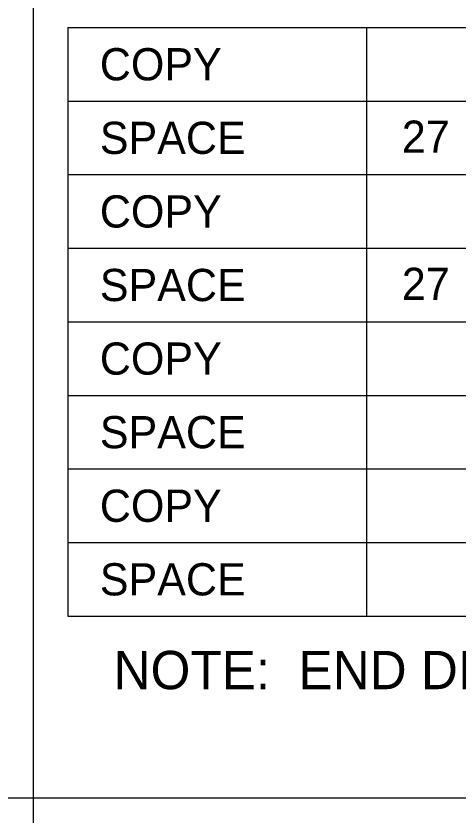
# Model space of a CAD drawing. Extents: x 10268312 to 10268472, y 2142583 to 2142688.
# Drawn here: x 10268394.36 to 10268403.97, y 2142639.91 to 2142657.28 of the extents above; entities that cross this region are included whole.
import ezdxf

# ---------------------------------------------------------------- set-up
doc = ezdxf.new("R2010")
doc.units = 0
for name, color, linetype in [('SheetBorder_dp', 7, 'Continuous'), ('SumBoxLines_dp', 7, 'Continuous'), ('SumBoxLinesMin_dp', 7, 'Continuous'), ('TextLabel', 7, 'Continuous'), ('TextMisc', 7, 'Continuous'), ('TextNotes', 7, 'Continuous')]:
    doc.layers.add(name, color=color, linetype=linetype)

msp = doc.modelspace()

# ---------------------------------------------------------------- linework, layer by layer
at = {"layer": 'SheetBorder_dp'}
for p, q in [((10268394.73, 2142688.282), (10268394.73, 2142592.282)), ((10268317.73, 2142640.282), (10268471.73, 2142640.282))]:
    msp.add_line(p, q, dxfattribs=at)
at = {"layer": 'SumBoxLines_dp'}
for p, q in [((10268395.48, 2142657.032), (10268470.98, 2142657.032)), ((10268395.48, 2142657.032), (10268395.48, 2142644.232)), ((10268401.98, 2142657.032), (10268401.98, 2142644.232)), ((10268395.48, 2142653.832), (10268470.98, 2142653.832)), ((10268395.48, 2142650.632), (10268470.98, 2142650.632)), ((10268395.48, 2142647.432), (10268470.98, 2142647.432)), ((10268395.48, 2142644.232), (10268470.98, 2142644.232))]:
    msp.add_line(p, q, dxfattribs=at)
at = {"layer": 'SumBoxLinesMin_dp'}
for p, q in [((10268395.48, 2142655.432), (10268470.98, 2142655.432)), ((10268395.48, 2142652.232), (10268470.98, 2142652.232)), ((10268395.48, 2142649.032), (10268470.98, 2142649.032)), ((10268395.48, 2142645.832), (10268470.98, 2142645.832))]:
    msp.add_line(p, q, dxfattribs=at)

# ---------------------------------------------------------------- texts
at = {"layer": 'TextLabel'}
for p in [(10268402.751, 2142654.307), (10268402.751, 2142651.107)]:
    msp.add_text('27', height=0.7, dxfattribs=at).set_placement(p)
at = {"layer": 'TextMisc'}
for s, p in [('COPY', (10268396.18, 2142655.882)), ('SPACE', (10268396.18, 2142654.282)), ('COPY', (10268396.18, 2142652.682)), ('SPACE', (10268396.18, 2142651.082)), ('COPY', (10268396.18, 2142649.482)), ('SPACE', (10268396.18, 2142647.882)), ('COPY', (10268396.18, 2142646.282)), ('SPACE', (10268396.18, 2142644.682))]:
    msp.add_text(s, height=0.7, dxfattribs=at).set_placement(p)
at = {"layer": 'TextNotes'}
msp.add_text('NOTE:  END DIMENSIONS INCLUDE BORDER WIDTH, MARGIN AND BORDER RECESS.  ', height=0.83333, dxfattribs=at).set_placement((10268396.479, 2142642.643))

doc.saveas('drawing.dxf')
